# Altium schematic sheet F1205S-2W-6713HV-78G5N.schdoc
size 277 x 190 mm; Device: default297x210; Symbol: default297x210; Name: default297x210; Date: 2026.06.26; Rev: V1.1; Size: "A4"; Id: /; File: F1205S-2W-6713HV-78G5N; Sheet: /; @Page No: 1; @Page Count: 1; @Schematic Name: F1205S-2W-6713HV-78G5N; @Project Name: 全桥隔离电源-F1205S-2W-6713HV-78G5N; @Board Name: F1205S-2W-6713HV-78G5N; @Update Date: 2025-07-23; @Create Time: 14:22:00; @Update Time: 10:21:26; @Page Name: F1205S-2W-6713HV-78G5N; @Create Date: 2025-06-26
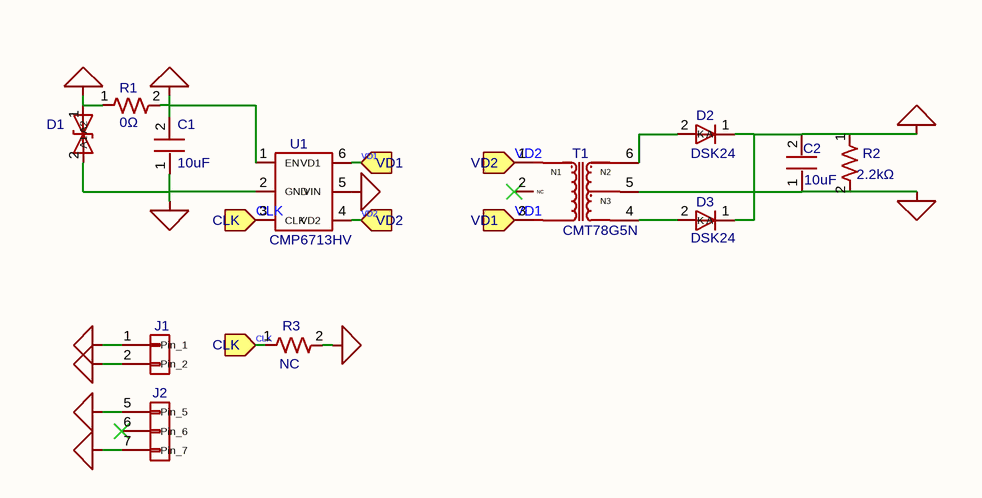
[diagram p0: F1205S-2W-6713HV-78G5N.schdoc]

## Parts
C1  10uF  [C0603]
C2  10uF  [C0603]
D1  (no value)  [SOD-123FL_L2.8-W1.8-LS3.7-BI]
D2  DSK24  [SOD-123_L2.8-W1.8-LS3.7-RD]
D3  DSK24  [SOD-123_L2.8-W1.8-LS3.7-RD]
J1  Connector_Generic_Conn_01x02  [coileasy:PinHeader_01x02_P2.54mm_Vertical]  (value not drawn)
J2  Connector_Generic_Conn_01x03  [coileasy:PinHeader_01x03_1_P2.54mm_Vertical]  (value not drawn)
R1  0Ω  [R0603]
R2  2.2kΩ  [R0603]
R3  NC  [R0603]
T1  CMT78G5N  [SMD-6_L9.7-W8.9-P2.54-LS12.8-TL]
U1  CMP6713HV  [coileasy:SOT-23-6]

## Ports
CLK (in), VD1 (in), VD2 (in)

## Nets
0V: C2.1 J2.5(Pin_5) R2.2 T1.5
+VO: C2.2 D2.1(K) D3.1(K) J2.7(Pin_7) R2.1
GND: C1.1 D1.2(A2) J1.2(Pin_2) R3.2 U1.2(GND)
VCC: C1.2 R1.2 U1.1(EN) U1.5(VIN)
VIN: D1.1(A1) J1.1(Pin_1) R1.1
CLK: R3.1 U1.3(CLK) ; port CLK
VD1: T1.3 U1.6(VD1) ; port VD1
VD2: T1.1 U1.4(VD2) ; port VD2
NetD2_2: D2.2(A) T1.6
NetD3_2: D3.2(A) T1.4

Not connected (* = marked no-connect by the designer): J2 6(Pin_6)*; T1 2*

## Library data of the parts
C1 = 0603X106M250NT: 容值:10uF;精度:±20%;额定电压:25V;温度系数:X5R;; Manufacturer: FH(风华); Symbol: My_Library_C; AddInBom: yes; ModelId: ac125912035d415993ca9572d50418b1; ModelName: C0603_L1.6-W0.8-H0.8; ModelTransform: 62.992,31.496,0,0,0,0,0,0,0; Tolerance: ±20%; Voltage Rating: 25V; Temperature Coefficient: X5R
C2 = 0603X106K100NT: 容值:10uF;精度:±10%;额定电压:10V;材质(温度系数):X5R;; Manufacturer: FH(风华); Symbol: My_Library_C; AddInBom: yes; ModelId: ac125912035d415993ca9572d50418b1; ModelName: C0603_L1.6-W0.8-H0.8; ModelTransform: 62.992,31.496,0,0,0,0,0,0,0; Tolerance: ±10%; Voltage Rated: 10V; Temperature Coefficient: X5R
D1 = SMF28CA_C364280: NC; Symbol: Device_D_TVS; AddInBom: yes; ModelId: d105299b3871451c86f679efef28ff8f; ModelTransform: 145.669,70.866,0,0,0,0,0,0,0; polarity: 双向; Type: TVS
D2 D3 = DSK24 K24: 二极管配置:独立式;正向压降(Vf):550mV@2A;直流反向耐压(Vr):40V;整流电流:2A;; Manufacturer: MDD(辰达半导体); Symbol: My_Library_D; AddInBom: yes; ModelId: 7884390a25fb4c08947731ebfba7e3f8; ModelTransform: 144.8816,62.992,0,0,0,0,0,0,0; Diode Configuration: 独立式; Reverse Voltage (Vr): 40V; Rectified Current: 2A; Reverse Leakage Current (Ir): 500uA@40V
J1 = Connector_Generic_Conn_01x02: Symbol: Conn_01x04_1; AddInBom: yes
J2 = Connector_Generic_Conn_01x03: Symbol: Connector_Generic_Conn_01x04; AddInBom: yes
R1 = RC0603FR-070RL: 电阻类型:厚膜电阻;阻值:0Ω;精度:±1%;功率:100mW;工作电压:75V;温度系数:-;; Manufacturer: YAGEO(国巨); Symbol: My_Library_R; AddInBom: yes; ModelId: fc143cca1e79419f9cd78b61e9279f08; ModelTransform: 31.8897,63.7794,0,90,0,0,0,0,0; Tolerance: ±1%; Power(Watts): 100mW; Voltage-Supply(Max): 75V
R2 = RC0603FR-072K2L: 电阻类型:厚膜电阻;阻值:2.2kΩ;精度:±1%;功率:100mW;工作电压:75V;温度系数:±100ppm/℃;; Manufacturer: YAGEO(国巨); Symbol: My_Library_R; AddInBom: yes; ModelId: fc143cca1e79419f9cd78b61e9279f08; ModelTransform: 31.8897,63.7794,0,90,0,0,0,0,0; Tolerance: ±1%; Power(Watts): 100mW; Voltage-Supply(Max): 75V
R3 = RC0603FR-0715KL: 电阻类型:厚膜电阻;阻值:15kΩ;精度:±1%;功率:100mW;最大工作电压:75V;温度系数:±100ppm/℃;; Symbol: My_Library_R; AddInBom: yes; ModelId: fc143cca1e79419f9cd78b61e9279f08; ModelTransform: 31.8897,63.7794,0,90,0,0,0,0,0; Tolerance: ±1%; Power(Watts): 100mW; Overload Voltage (Max): 75V
T1 = CMT78G5N: 电源变压器 SMD-6 隔离耐压：2.5KV 一次绕组：单路 二次绕组：双路 功率5W; Manufacturer: coileasy(线易); Symbol: MYLibrary _CMT6870N; AddInBom: yes
U1 = CMP6713HV: CMP6713HV 是全桥式变压器驱动器，芯片内部集成两个 N 型功率 MOSFET 和两个 P 型功率 MOSFET，通过内部振荡器提供具有精准时序和死区时间的互补驱动信号。驱动器搭配配套的变压器，可以实现输入电压6.5V-30V, 输出功率不超过 2W 的隔离电源。采用不同的变压器，外围只需搭配简单的输入输出滤波电容，隔离变压器和整流电路，即可获得多种电压的非稳压输出。产品提供电阻选频功能，可以在 200-420 kHz 范围内连续调整开关频率。; Manufacturer: coileasy(线易); Symbol: Coileasy_SOT23-6; AddInBom: yes; ModelId: 18da8f6c14a34920b3e136b5c401a119; ModelName: SOT-23-6_L2.9-W1.6-H1.5-LS2.8-P0.95; ModelTransform: 110.73671,114.173,0,180,0,0,0.001,-0.003,0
